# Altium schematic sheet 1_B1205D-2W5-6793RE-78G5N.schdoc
size 289 x 200 mm; Name: default297x210; Symbol: default297x210; Device: default297x210; Date: 2025.05.20; Rev: V1.0; Size: "A4"; File: B1205D-2W5-6793RE-78G5N; Sheet: /; @Page No: 1; @Page Count: 1; @Schematic Name: B1205D-2W5-6793RE-78G5N; @Project Name: B1205D-2W5-6793RE-78G5N; @Board Name: B1205D-2W5-6793RE-78G5N; @Update Date: 2025-05-28; @Create Time: 16:02:40; @Update Time: 15:25:28; @Page Name: B1205D-2W5-6793RE-78G5N; @Create Date: 2025-05-22
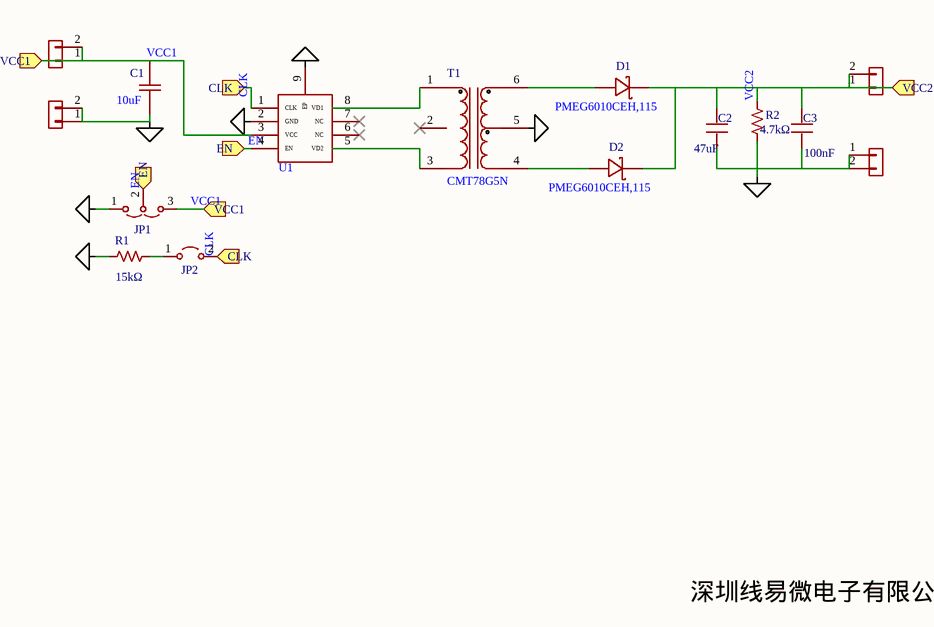
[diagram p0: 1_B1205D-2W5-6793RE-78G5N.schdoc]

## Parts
C1  10uF  [C0603]
C2  47uF  [C0805]
C3  100nF  [C0603]
D1  PMEG6010CEH,115  [SOD-123FL_L2.7-W1.8-LS3.8-RD]
D2  PMEG6010CEH,115  [SOD-123FL_L2.7-W1.8-LS3.8-RD]
J1  Connector_Generic_Conn_01x02  [Connector_PinHeader_2.54mm:PinHeader_1x02_P2.54mm_Vertical]  (value not drawn)
J2  Connector_Generic_Conn_01x02  [Connector_PinHeader_2.54mm:PinHeader_1x02_P2.54mm_Vertical]  (value not drawn)
J3  Connector_Generic_Conn_01x02  [Connector_PinHeader_2.54mm:PinHeader_1x02_P2.54mm_Vertical]  (value not drawn)
J4  Connector_Generic_Conn_01x02  [Connector_PinHeader_2.54mm:PinHeader_1x02_P2.54mm_Vertical]  (value not drawn)
JP1  Jumper_Jumper_3_Open  [Connector_PinHeader_2.54mm:PinHeader_1x03_P2.54mm_Vertical]  (value not drawn)
JP2  Jumper_Jumper_2_Open  [Connector_PinHeader_2.54mm:PinHeader_1x02_P2.54mm_Vertical]  (value not drawn)
R1  15kΩ  [R0603]
R2  4.7kΩ  [R0603]
T1  CMT78G5N  [SMD-6_L9.7-W8.9-P2.54-LS12.8-TL]
U1  (no value)  [ESOP-8_L4.9-W3.9-P1.27-LS6.2-BL-EP]

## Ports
CLK (in), EN (in), VCC1 (in), VCC2 (in)

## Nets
GND1: C1.1 J2.1(Pin_1) J2.2(Pin_2) JP1.1(A) R1.1 U1.2(GND) U1.9(EP)
GND2: C2.1 C3.1 J4.1(Pin_1) J4.2(Pin_2) R2.2 T1.5
CLK: JP2.2(B) U1.1(CLK) ; port CLK
EN: JP1.2(C) U1.4(EN) ; port EN
VCC1: C1.2 J1.1(Pin_1) J1.2(Pin_2) JP1.3(B) U1.3(VCC) ; port VCC1
VCC2: C2.2 C3.2 D1.1(C) D2.1(C) J3.1(Pin_1) J3.2(Pin_2) R2.1 ; port VCC2
NetD1_2: D1.2(A) T1.6
NetD2_2: D2.2(A) T1.4
NetJP2_1: JP2.1(A) R1.2
NetT1_1: T1.1 U1.8(VD1)
NetT1_3: T1.3 U1.5(VD2)

Not connected (* = marked no-connect by the designer): T1 2*; U1 6(NC)* 7(NC)*

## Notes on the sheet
- 深圳线易微电子有限公司

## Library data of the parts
C1 = 0603X106M250NT: Manufacturer: FH(风华); Add into BOM: yes; Tolerance: ±20%; Voltage Rating: 25V; Temperature Coefficient: X5R
C2 = CC0805MKX5R6BB476: Manufacturer: YAGEO(国巨); Symbol: My_Library_C; Add into BOM: yes; Tolerance: ±20%; Voltage Rating: 10V; Temperature Coefficient: X5R
C3 = CC0603KRX7R9BB104: Manufacturer: YAGEO(国巨); Symbol: My_Library_C; Add into BOM: yes; Tolerance: ±10%; Voltage Rated: 50V; Temperature Coefficient: X7R
D1 D2 = PMEG6010CEH,115: Manufacturer: Nexperia(安世); Add into BOM: yes; Forward Voltage (Vf@If): 660mV@1A; Reverse Voltage (Vr): 60V; Rectified Current: 1A; Reverse Leakage Current (Ir): 50uA@60V
J1-J4 = Connector_Generic_Conn_01x02: Users: REF**; sheetfile: EV_CMP6793SE.kicad_sch; Add into BOM: yes
JP1 = Jumper_Jumper_3_Open: Users: REF**; sheetfile: EV_CMP6793SE.kicad_sch; Add into BOM: yes
JP2 = Jumper_Jumper_2_Open: Add into BOM: yes
R1 = RC0603FR-0715KL: Manufacturer: YAGEO(国巨); Symbol: My_Library_R; Add into BOM: yes; Tolerance: ±1%; Power(Watts): 100mW; Overload Voltage (Max): 75V; Temperature Coefficient: ±100ppm/℃
R2 = RC0603FR-074K7L: Manufacturer: YAGEO(国巨); Symbol: My_Library_R; Add into BOM: yes; Tolerance: ±1%; Power(Watts): 100mW; Overload Voltage (Max): 75V; Temperature Coefficient: ±100ppm/℃
T1 = CMT78G5N: Manufacturer: coileasy(线易); Add into BOM: yes
U1 = CMP6793RE: Add into BOM: yes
